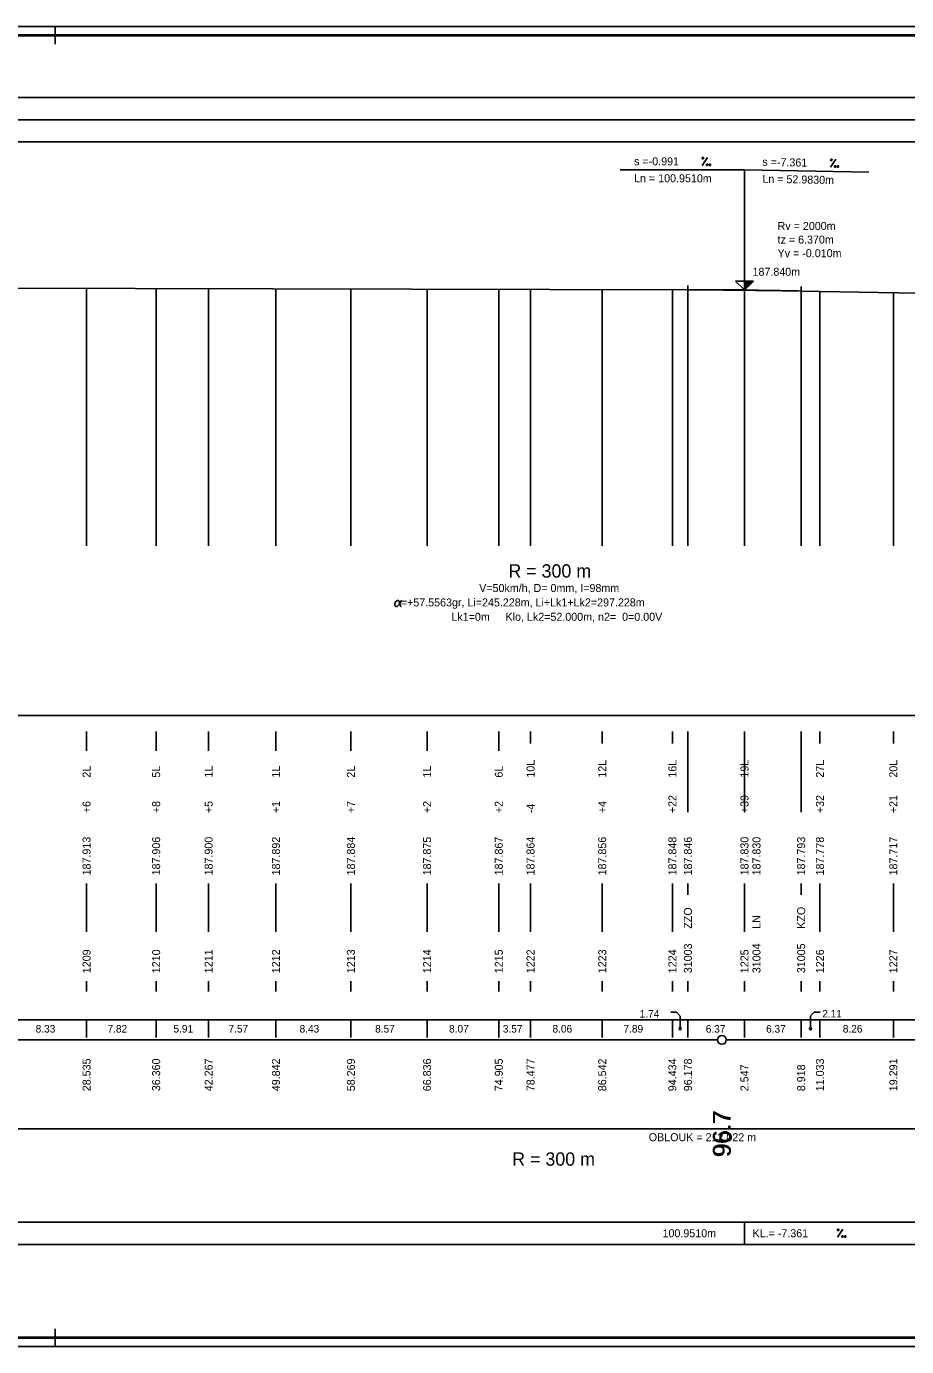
# Model space of a CAD drawing. Extents: x 0 to 10087, y -805 to 297.
# Drawn here: x 623.5 to 821.6, y 0 to 297 of the extents above; entities that cross this region are included whole.
import ezdxf

# ---------------------------------------------------------------- set-up
doc = ezdxf.new("R2010")
doc.units = 0
for name, color, linetype in [('CARKY_HODNOT', 7, 'Continuous'), ('KRIV1_CARA', 7, 'Continuous'), ('KRIV1_TEXT', 7, 'Continuous'), ('NIVELETA_CARA', 7, 'Continuous'), ('NIVELETA_TEXT', 7, 'Continuous'), ('PARAM_R', 7, 'Continuous'), ('PARAM_TEXT', 7, 'Continuous'), ('PREV_CARA', 7, 'Continuous'), ('RAM', 7, 'Continuous'), ('REZERVA', 7, 'Continuous'), ('STAN_CARA', 7, 'Continuous'), ('STAN_PAS', 7, 'Continuous'), ('STAN_TEXT', 7, 'Continuous'), ('TEXT', 7, 'Continuous'), ('TXT_C_BODU', 7, 'Continuous')]:
    doc.layers.add(name, color=color, linetype=linetype)

msp = doc.modelspace()

# ---------------------------------------------------------------- linework, layer by layer
at = {"layer": 'CARKY_HODNOT'}
for p, q in [((637.07, 180.14), (637.07, 238.07)), ((652.72, 180.14), (652.72, 238.03)), ((664.53, 180.14), (664.53, 238)), ((679.68, 180.14), (679.68, 237.96)), ((696.54, 180.14), (696.54, 237.92)), ((713.67, 180.14), (713.67, 237.88)), ((729.81, 180.14), (729.81, 237.84)), ((736.95, 180.14), (736.95, 237.82)), ((753.08, 180.14), (753.08, 237.78)), ((768.87, 180.14), (768.87, 237.74)), ((772.36, 180.14), (772.36, 237.73)), ((785.09, 180.14), (785.09, 237.65)), ((785.1, 180.14), (785.1, 237.65)), ((797.84, 180.14), (797.84, 237.47)), ((802.07, 180.14), (802.07, 237.39)), ((818.58, 180.14), (818.58, 237.08)), ((637.07, 134), (637.07, 138.35)), ((652.72, 134), (652.72, 138.35)), ((664.53, 134), (664.53, 138.35)), ((679.68, 134), (679.68, 138.35)), ((696.54, 134), (696.54, 138.35)), ((713.67, 134), (713.67, 138.35)), ((729.81, 134), (729.81, 138.35)), ((736.95, 135.65), (736.95, 138.35)), ((753.08, 135.65), (753.08, 138.35)), ((768.87, 135.65), (768.87, 138.35)), ((772.36, 126.2), (772.36, 138.35)), ((785.09, 135.65), (785.09, 138.35)), ((785.1, 126.2), (785.1, 138.35)), ((797.84, 126.2), (797.84, 138.35)), ((802.07, 135.65), (802.07, 138.35)), ((818.58, 135.65), (818.58, 138.35)), ((772.36, 120.25), (772.36, 126.2)), ((785.1, 120.25), (785.1, 126.2)), ((797.84, 120.25), (797.84, 126.2)), ((637.07, 93.3), (637.07, 104.2)), ((652.72, 93.3), (652.72, 104.2)), ((664.53, 93.3), (664.53, 104.2)), ((679.68, 93.3), (679.68, 104.2)), ((696.54, 93.3), (696.54, 104.2)), ((713.67, 93.3), (713.67, 104.2)), ((729.81, 93.3), (729.81, 104.2)), ((736.95, 93.3), (736.95, 104.2)), ((753.08, 93.3), (753.08, 104.2)), ((768.87, 93.3), (768.87, 104.2)), ((772.36, 101.65), (772.36, 104.2)), ((785.09, 93.3), (785.09, 104.2)), ((785.1, 100), (785.1, 104.2)), ((797.84, 101.65), (797.84, 104.2)), ((802.07, 93.3), (802.07, 104.2)), ((818.58, 93.3), (818.58, 104.2)), ((637.07, 79.9), (637.07, 82.2)), ((652.72, 79.9), (652.72, 82.2)), ((664.53, 79.9), (664.53, 82.2)), ((679.68, 79.9), (679.68, 82.2)), ((696.54, 79.9), (696.54, 82.2)), ((713.67, 79.9), (713.67, 82.2)), ((729.81, 79.9), (729.81, 82.2)), ((736.95, 79.9), (736.95, 82.2)), ((753.08, 79.9), (753.08, 82.2)), ((768.87, 79.9), (768.87, 82.2)), ((772.36, 79.9), (772.36, 82.2)), ((785.09, 79.9), (785.09, 82.2)), ((785.1, 79.9), (785.1, 82.2)), ((797.84, 79.9), (797.84, 82.2)), ((802.07, 79.9), (802.07, 82.2)), ((818.58, 79.9), (818.58, 82.2))]:
    msp.add_line(p, q, dxfattribs=at)
at = {"layer": 'KRIV1_CARA'}
msp.add_line((566.39, 49), (990.43, 49), dxfattribs=at)
at = {"layer": 'NIVELETA_CARA'}
for p, q in [((300, 281), (8321.33, 281)), ((300, 276), (8321.33, 276)), ((300, 271), (8321.33, 271)), ((785.1, 264.7), (757.1, 264.77)), ((785.1, 237.7), (785.1, 264.7)), ((785.1, 264.7), (813.1, 264.18)), ((590.8, 238.18), (772.36, 237.73)), ((772.36, 237.73), (772.36, 238.73)), ((772.36, 237.73), (785.1, 237.7)), ((772.36, 237.73), (772.86, 237.73)), ((772.86, 237.73), (773.36, 237.73)), ((773.36, 237.73), (773.86, 237.73)), ((773.86, 237.73), (774.36, 237.73)), ((774.36, 237.73), (774.86, 237.72)), ((774.86, 237.72), (775.36, 237.72)), ((775.36, 237.72), (775.86, 237.72)), ((775.86, 237.72), (776.36, 237.72)), ((776.36, 237.72), (776.86, 237.71)), ((776.86, 237.71), (777.36, 237.71)), ((777.36, 237.71), (777.86, 237.71)), ((777.86, 237.71), (778.36, 237.71)), ((778.36, 237.71), (778.86, 237.7)), ((778.86, 237.7), (779.36, 237.7)), ((779.36, 237.7), (779.86, 237.7)), ((779.86, 237.7), (780.36, 237.69)), ((780.36, 237.69), (780.86, 237.69)), ((780.86, 237.69), (781.36, 237.68)), ((781.36, 237.68), (781.86, 237.68)), ((781.86, 237.68), (782.36, 237.68)), ((782.36, 237.68), (782.86, 237.67)), ((782.86, 237.67), (783.36, 237.67)), ((785.1, 237.7), (783.1, 239.7)), ((783.1, 239.7), (787.1, 239.7)), ((783.36, 237.67), (783.86, 237.66)), ((783.86, 237.66), (784.36, 237.66)), ((784.36, 237.66), (784.86, 237.65)), ((784.86, 237.65), (785.1, 237.65)), ((785.1, 237.7), (785.1, 239.7)), ((787.1, 239.7), (785.1, 237.7)), ((785.1, 237.7), (797.84, 237.47)), ((785.1, 237.65), (785.6, 237.64)), ((785.16, 237.77), (785.16, 239.7)), ((785.23, 237.83), (785.23, 239.7)), ((785.3, 237.9), (785.3, 239.7)), ((785.36, 237.97), (785.36, 239.7)), ((785.43, 238.03), (785.43, 239.7)), ((785.5, 238.1), (785.5, 239.7)), ((785.56, 238.17), (785.56, 239.7)), ((785.6, 237.64), (786.1, 237.64)), ((785.63, 238.23), (785.63, 239.7)), ((785.7, 238.3), (785.7, 239.7)), ((785.76, 238.37), (785.76, 239.7)), ((785.83, 238.43), (785.83, 239.7)), ((785.9, 238.5), (785.9, 239.7)), ((785.96, 238.57), (785.96, 239.7)), ((786.03, 238.63), (786.03, 239.7)), ((786.1, 238.7), (786.1, 239.7)), ((786.1, 237.64), (786.6, 237.63)), ((786.16, 238.77), (786.16, 239.7)), ((786.23, 238.83), (786.23, 239.7)), ((786.3, 238.9), (786.3, 239.7)), ((786.36, 238.97), (786.36, 239.7)), ((786.43, 239.03), (786.43, 239.7)), ((786.5, 239.1), (786.5, 239.7)), ((786.56, 239.17), (786.56, 239.7)), ((786.6, 237.63), (787.1, 237.63)), ((786.63, 239.23), (786.63, 239.7)), ((786.7, 239.3), (786.7, 239.7)), ((786.76, 239.37), (786.76, 239.7)), ((786.83, 239.43), (786.83, 239.7)), ((786.9, 239.5), (786.9, 239.7)), ((786.96, 239.57), (786.96, 239.7)), ((787.03, 239.63), (787.03, 239.7)), ((787.1, 237.63), (787.6, 237.62)), ((787.6, 237.62), (788.1, 237.62)), ((788.1, 237.62), (788.6, 237.61)), ((788.6, 237.61), (789.1, 237.6)), ((789.1, 237.6), (789.6, 237.6)), ((797.84, 237.47), (797.84, 238.47)), ((789.6, 237.6), (790.1, 237.59)), ((790.1, 237.59), (790.6, 237.58)), ((790.6, 237.58), (791.1, 237.58)), ((791.1, 237.58), (791.6, 237.57)), ((791.6, 237.57), (792.1, 237.56)), ((792.1, 237.56), (792.6, 237.55)), ((792.6, 237.55), (793.1, 237.55)), ((793.1, 237.55), (793.6, 237.54)), ((793.6, 237.54), (794.1, 237.53)), ((794.1, 237.53), (794.6, 237.52)), ((794.6, 237.52), (795.1, 237.51)), ((795.1, 237.51), (795.6, 237.51)), ((795.6, 237.51), (796.1, 237.5)), ((796.1, 237.5), (796.6, 237.49)), ((796.6, 237.49), (797.1, 237.48)), ((797.1, 237.48), (797.6, 237.47)), ((797.6, 237.47), (797.84, 237.47)), ((797.84, 237.47), (885.08, 235.86)), ((500, 28), (8321.33, 28)), ((785.1, 23), (785.1, 28)), ((500, 23), (8321.33, 23))]:
    msp.add_line(p, q, dxfattribs=at)
at = {"layer": 'NIVELETA_TEXT'}
for p, q in [((775.6, 265.73), (776.79, 267.52)), ((775.6, 267.52), (775.6, 267.22)), ((775.61, 267.52), (775.6, 267.51)), ((775.9, 267.52), (775.61, 267.52)), ((775.9, 267.22), (775.9, 267.52)), ((775.6, 267.22), (775.9, 267.22)), ((776.51, 266.02), (776.51, 265.72)), ((776.81, 266.02), (776.51, 266.02)), ((776.51, 266.02), (776.51, 266.02)), ((776.51, 265.72), (776.8, 265.72)), ((776.8, 265.72), (776.81, 266.02)), ((777.12, 266.02), (777.12, 265.72)), ((777.13, 266.02), (777.12, 266.01)), ((777.12, 265.72), (777.42, 265.72)), ((777.42, 266.02), (777.13, 266.02)), ((777.42, 265.72), (777.42, 266.02)), ((804.45, 265.35), (805.67, 267.12)), ((804.48, 267.14), (804.47, 266.84)), ((804.47, 266.84), (804.77, 266.84)), ((804.78, 267.13), (804.48, 267.14)), ((804.48, 267.14), (804.48, 267.13)), ((804.77, 266.84), (804.78, 267.13)), ((805.36, 265.63), (805.35, 265.33)), ((805.35, 265.33), (805.65, 265.32)), ((805.37, 265.63), (805.36, 265.62)), ((805.66, 265.62), (805.37, 265.63)), ((805.65, 265.32), (805.66, 265.62)), ((805.97, 265.62), (805.97, 265.32)), ((805.98, 265.62), (805.97, 265.61)), ((805.97, 265.32), (806.27, 265.31)), ((806.27, 265.61), (805.98, 265.62)), ((806.27, 265.31), (806.27, 265.61)), ((806.05, 24.6), (807.24, 26.4)), ((806.05, 26.4), (806.05, 26.1)), ((806.35, 26.4), (806.05, 26.4)), ((806.05, 26.4), (806.05, 26.39)), ((806.05, 26.1), (806.35, 26.1)), ((806.35, 26.1), (806.35, 26.4)), ((806.96, 24.9), (806.96, 24.6)), ((807.25, 24.9), (806.96, 24.9)), ((806.96, 24.9), (806.96, 24.89)), ((806.96, 24.6), (807.25, 24.6)), ((807.25, 24.6), (807.25, 24.9)), ((807.57, 24.9), (807.57, 24.6)), ((807.58, 24.9), (807.57, 24.89)), ((807.57, 24.6), (807.87, 24.6)), ((807.87, 24.9), (807.58, 24.9)), ((807.87, 24.6), (807.87, 24.9))]:
    msp.add_line(p, q, dxfattribs=at)
at = {"layer": 'PARAM_TEXT'}
for p, q in [((706.43, 167.11), (706.52, 167.39)), ((706.43, 166.81), (706.43, 167.11)), ((706.52, 166.62), (706.43, 166.81)), ((706.52, 167.39), (706.62, 167.59)), ((706.72, 166.52), (706.52, 166.62)), ((706.62, 167.59), (706.82, 167.79)), ((706.92, 166.52), (706.72, 166.52)), ((706.82, 167.79), (707.01, 167.88)), ((707.11, 166.62), (706.92, 166.52)), ((707.01, 167.88), (707.19, 167.89)), ((707.41, 166.92), (707.11, 166.62)), ((707.19, 167.89), (707.31, 167.78)), ((707.31, 167.78), (707.41, 167.59)), ((707.41, 167.59), (707.6, 166.81)), ((707.61, 167.21), (707.41, 166.92)), ((707.6, 166.81), (707.7, 166.62)), ((707.7, 167.41), (707.61, 167.21)), ((707.8, 167.6), (707.7, 167.41)), ((707.7, 166.62), (707.8, 166.52)), ((707.89, 167.89), (707.8, 167.6)), ((707.8, 166.52), (707.88, 166.52))]:
    msp.add_line(p, q, dxfattribs=at)
at = {"layer": 'PREV_CARA'}
msp.add_line((499.98, 142), (990.43, 142), dxfattribs=at)
at = {"layer": 'RAM'}
for p, q in [((8636.33, 297), (0, 297)), ((630, 293), (630, 297)), ((8634.33, 295.1), (2, 295.1)), ((8634.33, 295), (2, 295)), ((8634.33, 294.9), (2, 294.9)), ((630, 0), (630, 4)), ((0, 0), (8636.33, 0)), ((2, 2.1), (8634.33, 2.1)), ((2, 2), (8634.33, 2)), ((2, 1.9), (8634.33, 1.9))]:
    msp.add_line(p, q, dxfattribs=at)
at = {"layer": 'REZERVA'}
msp.add_circle((780, 69), 1, dxfattribs=at)
at = {"layer": 'STAN_CARA'}
for p, q in [((581, 69), (779, 69)), ((781, 69), (979, 69))]:
    msp.add_line(p, q, dxfattribs=at)
at = {"layer": 'STAN_PAS'}
for p, q in [((769.76, 75.2), (768.49, 75.2)), ((770.61, 74.35), (769.76, 75.2)), ((770.61, 71.75), (770.61, 74.35)), ((799.95, 74.4), (800.8, 75.25)), ((799.95, 71.75), (799.95, 74.35)), ((800.8, 75.25), (802.08, 75.25)), ((300, 73.5), (8321.33, 73.5)), ((637.07, 69.5), (637.07, 73.5)), ((652.72, 69.5), (652.72, 73.5)), ((664.53, 69.5), (664.53, 73.5)), ((679.68, 69.5), (679.68, 73.5)), ((696.54, 69.5), (696.54, 73.5)), ((713.67, 69.5), (713.67, 73.5)), ((729.81, 69.5), (729.81, 73.5)), ((736.95, 69.5), (736.95, 73.5)), ((753.08, 69.5), (753.08, 73.5)), ((768.87, 69.5), (768.87, 73.5)), ((772.36, 69.5), (772.36, 73.5)), ((785.09, 69.5), (785.09, 73.5)), ((785.1, 69.5), (785.1, 73.5)), ((797.84, 69.5), (797.84, 73.5)), ((802.07, 69.5), (802.07, 73.5)), ((818.58, 69.5), (818.58, 73.5))]:
    msp.add_line(p, q, dxfattribs=at)
for centre in [(770.61, 71.5), (799.95, 71.5)]:
    msp.add_circle(centre, 0.25, dxfattribs=at)

# ---------------------------------------------------------------- texts
at = {"layer": 'KRIV1_TEXT'}
msp.add_text('OBLOUK = 212.022 m', height=1.8, dxfattribs=at).set_placement((763.56, 46.2))
at = {"layer": 'NIVELETA_TEXT'}
for s, rotation, p in [('s =-0.991', 359.8581, (760.25, 265.76)), ('s =-7.361', 358.9458, (789.1, 265.63)), ('Ln = 100.9510m', 359.8581, (760.25, 261.96)), ('Ln = 52.9830m', 358.9458, (789.1, 261.83))]:
    msp.add_text(s, height=1.8, rotation=rotation, dxfattribs=at).set_placement(p)
for s, p in [('Rv = 2000m', (792.54, 251.2)), ('tz = 6.370m', (792.54, 248.14)), ('Yv = -0.010m', (792.54, 245.08)), ('187.840m', (786.9, 240.9)), ('100.9510m', (766.65, 24.6)), ('KL.= -7.361', (786.9, 24.6))]:
    msp.add_text(s, height=1.8, dxfattribs=at).set_placement(p)
at = {"layer": 'PARAM_R'}
for p in [(731.97, 173), (732.83, 40.7)]:
    msp.add_text('R = 300 m', height=3, dxfattribs=at).set_placement(p)
at = {"layer": 'PARAM_TEXT'}
for s, p in [('V=50km/h, D= 0mm, I=98mm', (725.4, 169.76)), ('  =+57.5563gr, Li=245.228m, Li+Lk1+Lk2=297.228m', (706.43, 166.52)), ('Lk1=0m', (719.15, 163.28)), ('Klo, Lk2=52.000m, n2=  0=0.00V', (731.33, 163.28))]:
    msp.add_text(s, height=1.8, dxfattribs=at).set_placement(p)
at = {"layer": 'STAN_TEXT'}
for s, p in [('1.74', (761.51, 74.01)), ('2.11', (802.58, 74.04)), ('8.33', (625.62, 70.65)), ('7.82', (641.78, 70.65)), ('5.91', (656.61, 70.65)), ('7.57', (668.99, 70.65)), ('8.43', (684.99, 70.65)), ('8.57', (701.99, 70.65)), ('8.07', (718.62, 70.65)), ('3.57', (730.72, 70.64)), ('8.06', (741.9, 70.65)), ('7.89', (757.86, 70.65)), ('6.37', (776.38, 70.62)), ('6.37', (789.95, 70.63)), ('8.26', (807.21, 70.65))]:
    msp.add_text(s, height=1.7, dxfattribs=at).set_placement(p)
for s, height, p in [('28.535', 1.8, (637.97, 57.45)), ('36.360', 1.8, (653.62, 57.45)), ('42.267', 1.8, (665.43, 57.45)), ('49.842', 1.8, (680.58, 57.45)), ('58.269', 1.8, (697.44, 57.45)), ('66.836', 1.8, (714.57, 57.45)), ('74.905', 1.8, (730.71, 57.45)), ('78.477', 1.8, (737.85, 57.45)), ('86.542', 1.8, (753.98, 57.45)), ('94.434', 1.8, (769.77, 57.45)), ('96.178', 1.8, (773.26, 57.45)), ('2.547', 1.8, (785.99, 57.45)), ('8.918', 1.8, (798.74, 57.45)), ('11.033', 1.8, (802.97, 57.45)), ('19.291', 1.8, (819.48, 57.45)), ('    96.7', 4, (782, 36.84)), ('    96.7', 4, (782, 36.74)), ('    96.7', 4, (782, 36.64))]:
    msp.add_text(s, height=height, rotation=90, dxfattribs=at).set_placement(p)
at = {"layer": 'TEXT'}
for s, p in [('10L', (737.85, 128)), ('12L', (753.98, 128)), ('16L', (769.77, 128)), ('19L', (785.99, 128)), ('27L', (802.97, 128)), ('20L', (819.48, 128)), ('2L', (637.97, 128)), ('5L', (653.62, 128)), ('1L', (665.43, 128)), ('1L', (680.58, 128)), ('2L', (697.44, 128)), ('1L', (714.57, 128)), ('6L', (730.71, 128)), ('+6', (637.97, 120)), ('+8', (653.62, 120)), ('+5', (665.43, 120)), ('+1', (680.58, 120)), ('+7', (697.44, 120)), ('+2', (714.57, 120)), ('+2', (730.71, 120)), ('-4', (737.85, 120)), ('+4', (753.98, 120)), ('+22', (769.77, 120)), ('+39', (785.99, 120)), ('+32', (802.97, 120)), ('+21', (819.48, 120)), ('187.913', (637.97, 106)), ('187.906', (653.62, 106)), ('187.900', (665.43, 106)), ('187.892', (680.58, 106)), ('187.884', (697.44, 106)), ('187.875', (714.57, 106)), ('187.867', (730.71, 106)), ('187.864', (737.85, 106)), ('187.856', (753.98, 106)), ('187.848', (769.77, 106)), ('187.846', (773.26, 106)), ('187.830', (785.99, 106)), ('187.830', (788.69, 106)), ('187.793', (798.74, 106)), ('187.778', (802.97, 106)), ('187.717', (819.48, 106)), ('ZZO', (773.26, 94)), ('KZO', (798.74, 94)), ('LN', (788.69, 94))]:
    msp.add_text(s, height=1.8, rotation=90, dxfattribs=at).set_placement(p)
at = {"layer": 'TXT_C_BODU'}
for s, p in [('1209', (637.97, 84)), ('1210', (653.62, 84)), ('1211', (665.43, 84)), ('1212', (680.58, 84)), ('1213', (697.44, 84)), ('1214', (714.57, 84)), ('1215', (730.71, 84)), ('1222', (737.85, 84)), ('1223', (753.98, 84)), ('1224', (769.77, 84)), ('31003', (773.26, 84)), ('1225', (785.99, 84)), ('31004', (788.69, 84)), ('31005', (798.74, 84)), ('1226', (802.97, 84)), ('1227', (819.48, 84))]:
    msp.add_text(s, height=1.8, rotation=90, dxfattribs=at).set_placement(p)

doc.saveas('drawing.dxf')
